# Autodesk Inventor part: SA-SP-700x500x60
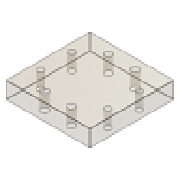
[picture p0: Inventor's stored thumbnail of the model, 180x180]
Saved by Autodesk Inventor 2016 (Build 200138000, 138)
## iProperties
Created: 2015-02
Part Number: SA-SP-700x500x60
Material: S 55 C
Description: Support Plate
Document SubType Name: Modeling
Designer: Sandeep
Standard Revision: 1
Manufacturer: FUTABA
Language: en-US
Size Designation: 700x500x60
Categories: <MemberInstance><Categories><Category DisplayName="Mold" InternalName="349578f2-f4d4-4954-8c09-8e99297a61c0" Mnemonic="MOLD"><Category DisplayName="Mold Plates"
Density: 7.85 g/cm^3
Appearance: Polycarbonate - Smoked
IsCustomPart: 1
Author: Sandeep
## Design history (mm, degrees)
sketch "Sketch1"
  geometry: L1 (-250, 350)-(250, 350); L2 (250, 350)-(250, -350); L3 (250, -350)-(-250, -350); L4 (-250, -350)-(-250, 350); 5 further points
  constraints: 8 end point, 2 midpoint, 2 parallel, 1 horizontal, 1 horizontal alignment, 1 perpendicular, 1 vertical alignment
  dimensions: "d68" = 500 distance between parallel lines of L2 L4 (= W_); "d69" = 700 distance between parallel lines of L3 L1 (= L); "d70" = 317 vertical distance of point (0, 0) point (-128, 317) (= 0.5 x RP_L); "d71" = 128 horizontal distance of point (0, 0) point (-128, 317) (= 0.5 x RP_W); "d72" = 243 vertical distance of point (0, 0) point (-205, 243) (= 0.5 x S1_L); "d73" = 205 horizontal distance of point (0, 0) point (-205, 243) (= 0.5 x S1_W)
extrude "Extrusion1" new body sketch "Sketch1" distance "d20" = 60 (= H_); taper "d30" = 0 deg
body "Solid1"
hole "Hole1" sketch "Sketch1" diameter "d74" = 18 (= S1_d1); stored, may be unused: countersink angle "d78" = 90 deg, drill point angle "d80" = 0 deg; dims "d75" = 6, "d76" = 4, "d77" = 2, "d79" = 60 (= H_)
pattern_linear "Rectangular Pattern1" dims "d102" = 243 (computed from S1_L, Ns)
hole "Hole2" sketch "Sketch1" diameter "d81" = 31 (= RP_d1); stored, may be unused: countersink angle "d85" = 90 deg, drill point angle "d87" = 0 deg; dims "d82" = 6, "d83" = 4, "d84" = 2, "d86" = 60 (= H_)
pattern_linear "Rectangular Pattern2" dims "d108" = 634 (computed from RP_L, Nl), "d111" = 256 (computed from RP_W, Nw)
chamfer "Chamfer1" distance "d112" = 0.5; stored, may be unused: second distance "d113" = 2, angle "d114" = 45 deg
other parameters: "L" = 700 [user parameter; used in 1 equation term], "W_" = 500 [user parameter; used in 1 equation term], "H_" = 60 [user parameter; used in 3 equation terms], "RP_W" = 256 [user parameter; used in 2 equation terms], "S1_d1" = 18 [user parameter; used in 1 equation term], "RP_d1" = 31 [user parameter; used in 1 equation term], "S1_L" = 486 [user parameter; used in 2 equation terms], "RP_L" = 634 [user parameter; used in 2 equation terms]
